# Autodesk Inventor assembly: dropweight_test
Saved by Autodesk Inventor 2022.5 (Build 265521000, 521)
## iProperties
Created: 2024-07
Part Number: dropweight_test
Document SubType Name: Assembly
Designer: AdminForWorker
Title: dropweight_test v4
Author: AdminForWorker
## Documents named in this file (6)
- c:\worker\convert-fusion-r03-cosv3\tmp\job-1\9\temp\files\bbec2215-04f0-41ff-9f36-3edec64e4d7e\b343193e-7f0b-47b0-b241-4c61958027de.iam
- c:\worker\convert-fusion-r03-cosv3\tmp\job-1\9\temp\files\bbec2215-04f0-41ff-9f36-3edec64e4d7e\Board.ipt
- c:\worker\convert-fusion-r03-cosv3\tmp\job-1\9\temp\files\bbec2215-04f0-41ff-9f36-3edec64e4d7e\1-copper.ipt
- c:\worker\convert-fusion-r03-cosv3\tmp\job-1\9\temp\files\bbec2215-04f0-41ff-9f36-3edec64e4d7e\16-copper.ipt
- c:\worker\convert-fusion-r03-cosv3\tmp\job-1\9\temp\files\bbec2215-04f0-41ff-9f36-3edec64e4d7e\1-soldermask.ipt
- c:\worker\convert-fusion-r03-cosv3\tmp\job-1\9\temp\files\bbec2215-04f0-41ff-9f36-3edec64e4d7e\16-soldermask.ipt
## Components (5 placed, 5 different names)
1. Board:1
2. 1-copper:1
3. 16-copper:1
4. 1-soldermask:1
5. 16-soldermask:1
